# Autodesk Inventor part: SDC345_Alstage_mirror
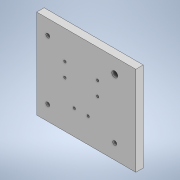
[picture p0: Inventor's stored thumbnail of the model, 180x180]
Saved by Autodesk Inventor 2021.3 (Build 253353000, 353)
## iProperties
Created: 2022-02
Part Number: SDC345_Alstage_mirror
Material: 一般
Document SubType Name: Modeling
Designer: kengo
Density: 1 g/cm^3
Appearance: 既定
Author: kengo
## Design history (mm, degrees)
derived "SDC345_Alstage.ipt"
feature "ソリッド1::SDC345_Alstage.ipt" dims "d0" = 10
tag "TaggingFeature1"
node "ソリッド1"
